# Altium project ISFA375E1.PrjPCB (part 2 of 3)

## Sheet ISFA375_DS_USB-C_CONN.SchDoc
size 431 x 279 mm; Date: Not shown in title block; ApprovedBy: Not shown in title block; CheckedBy: Not shown in title block; Author: Not shown in title block; CompanyName: Not shown in title block; DrawnBy: Thomas Mauer; Engineer: Not shown in title block; Organization: Not shown in title block; Address1: Not shown in title block; Address2: Not shown in title block; Address3: Not shown in title block; Address4: Not shown in title block; DocumentNumber: 4; Revision: Use project parameter SCH_Rev; SheetNumber: 4; SheetTotal: 11; PageSetup: Record=PageOptions¦CenterHorizontal=True¦CenterVertical=True¦PrintScale=1.00¦XCorrection=1.00¦YCorrection=1.00¦PrintKind=0¦BorderSize=5000000¦LeftOffset=0¦BottomOffset=0¦Orientation=2¦PaperLength=1000¦PaperWidth=1000¦Scale=100¦PaperSource=15¦PrintQuality=600¦MediaType=1¦DitherType=10¦PaperKind=Letter¦PrintScaleMode=1
Used 2 times, as channels DS1, DS2. Parts and nets are listed once, with the designators drawn on the sheet.
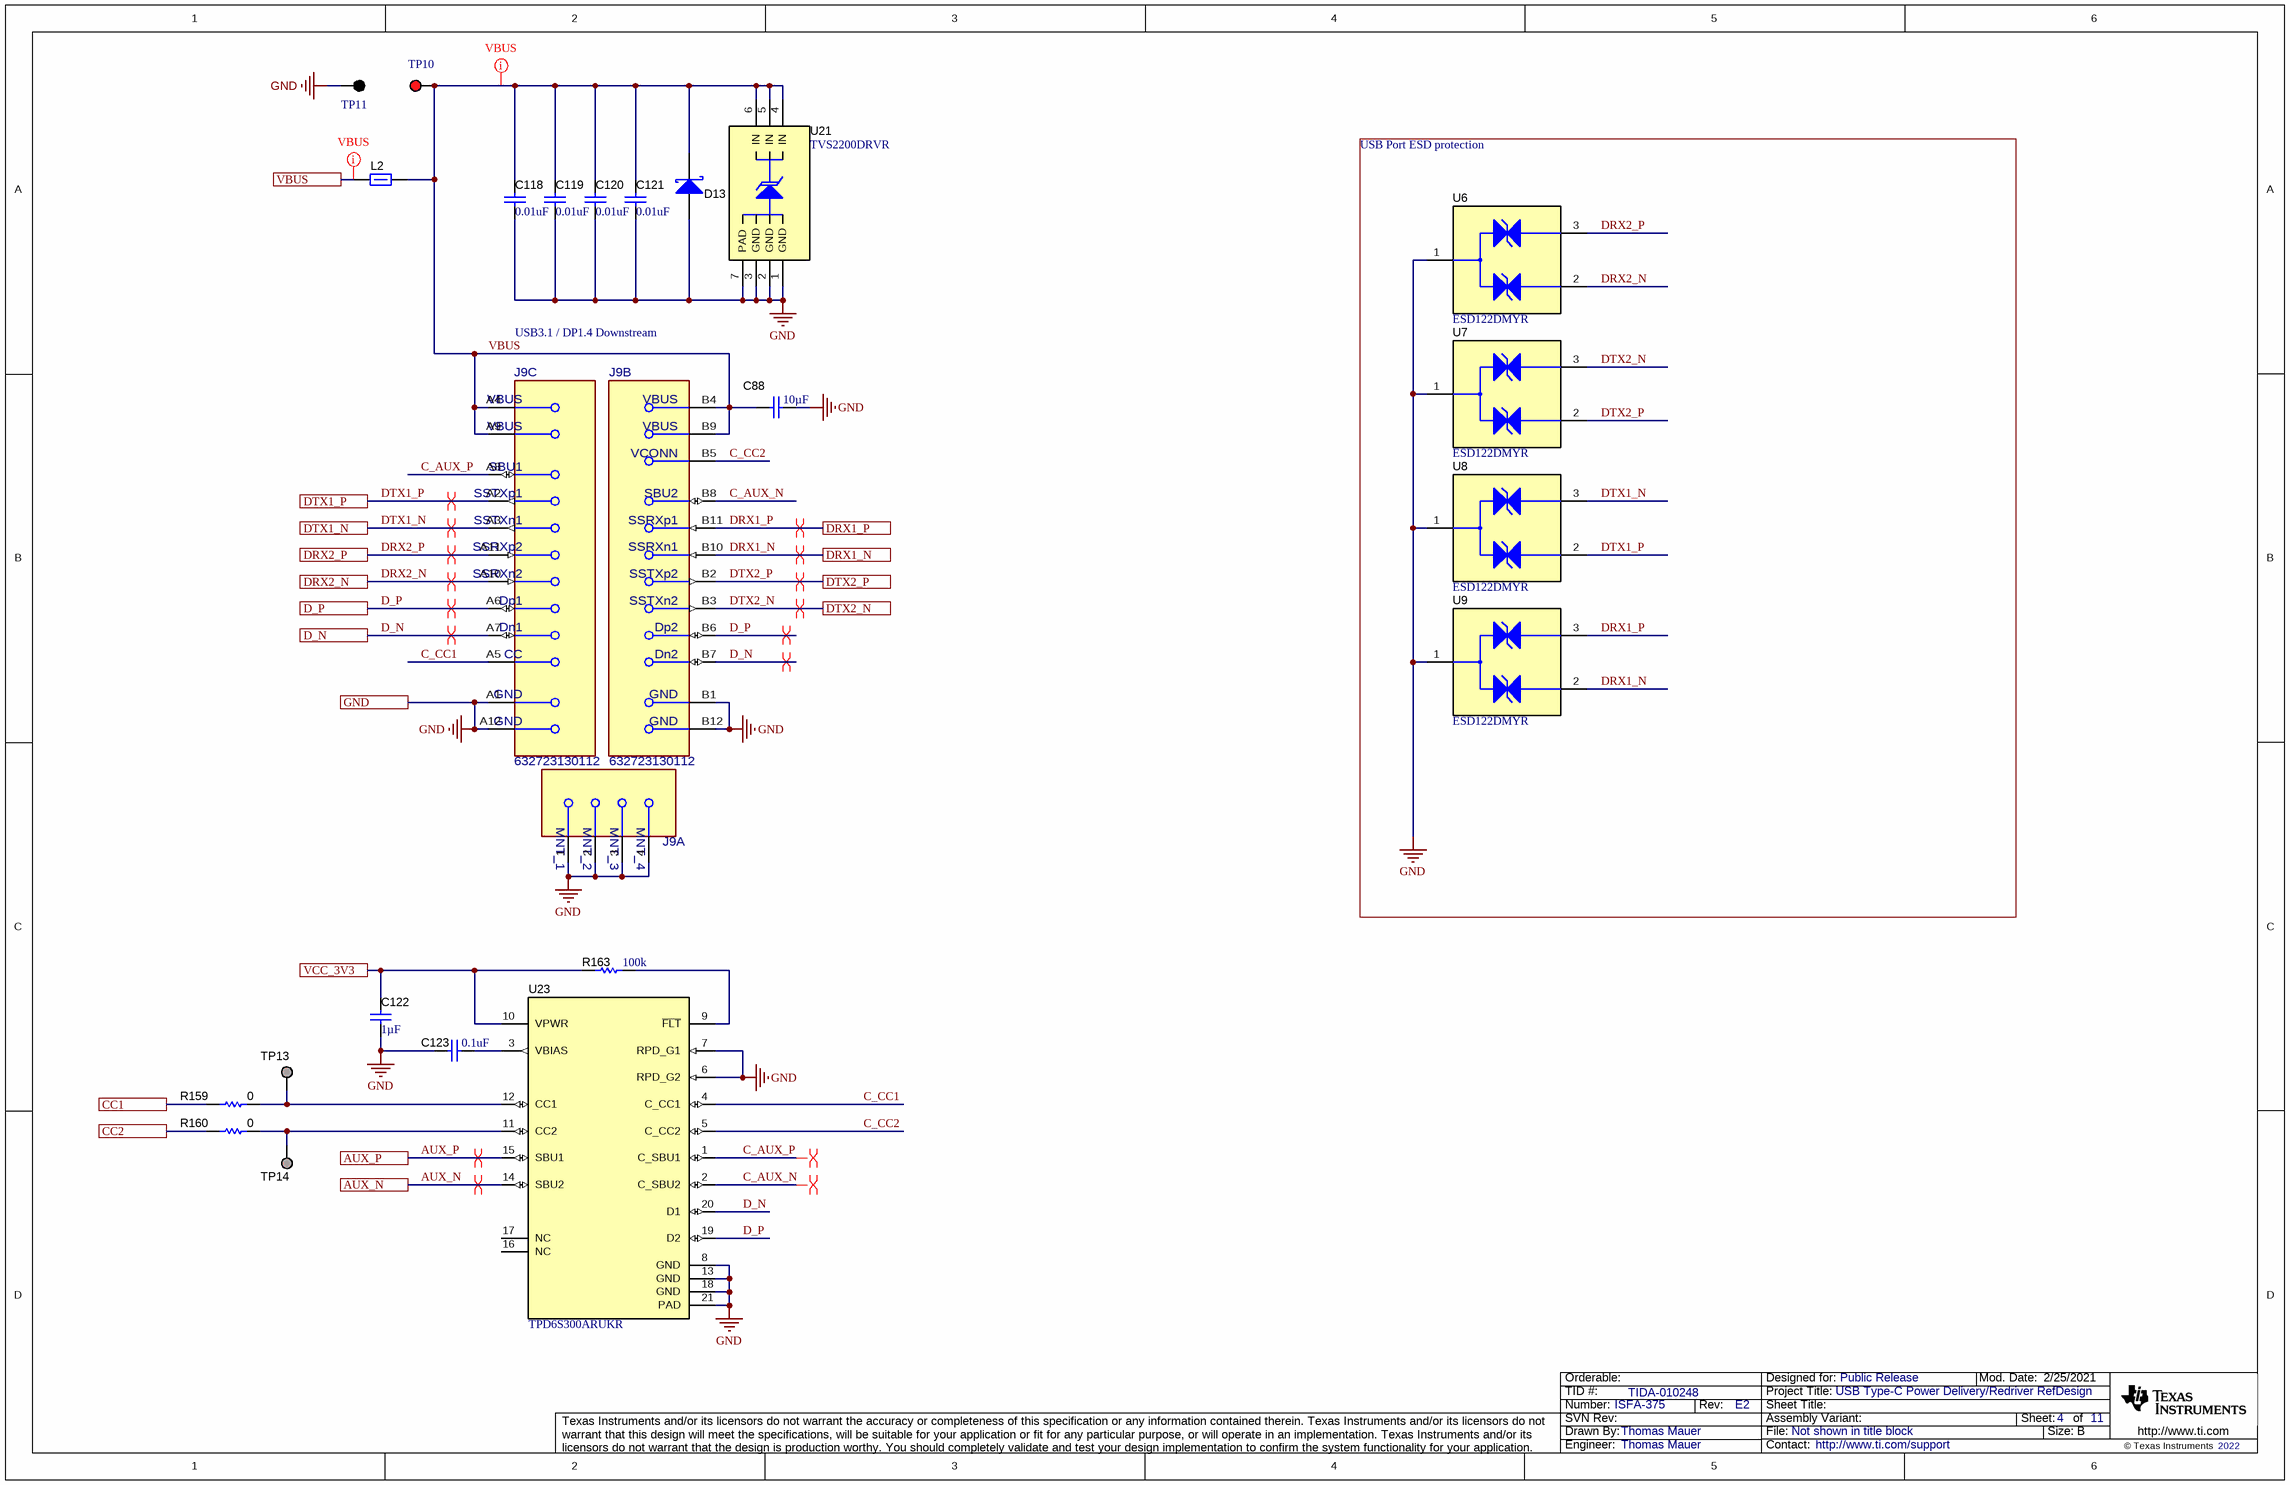
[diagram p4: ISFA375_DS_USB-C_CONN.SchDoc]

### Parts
C88  Cap_F: 10µF  [0805L]  (hidden comment: CL21B106KOQNNNE)
C118  ValueDisplayed: 0.01uF  [0402L]  (hidden comment: C0402C103J5RACTU)
C119  ValueDisplayed: 0.01uF  [0402L]  (hidden comment: C0402C103J5RACTU)
C120  ValueDisplayed: 0.01uF  [0402L]  (hidden comment: C0402C103J5RACTU)
C121  ValueDisplayed: 0.01uF  [0402L]  (hidden comment: C0402C103J5RACTU)
C122  ValueDisplayed: 1µF  [0603L]  (hidden comment: GRT188R61H105ME13D)
C123  ValueDisplayed: 0.1uF  [0402L]  (hidden comment: CGA2B3X7R1H104K050BB)
D13  NSR20F30NXT5G  [DSN2_0603]  (value not drawn)
J9  632723130112  [FP-632723130112_CONN_USB_9MM65_10MM0-MFG]  (value not drawn)  (parts A,B,C of 3)
L2  742792021  [0805L]  (value not drawn)
R159  ValueDisplayed: 0  [0201L]  (hidden comment: CRCW02010000Z0ED)
R160  ValueDisplayed: 0  [0201L]  (hidden comment: CRCW02010000Z0ED)
R163  ValueDisplayed: 100k  [0201L]  (hidden comment: CRCW0201100KFKED)
TP10  5005  [Keystone5005]  (value not drawn)
TP11  5006  [Keystone5006]  (value not drawn)
TP13  TESTPOINT  [TP_25MIL-SMT]  (value not drawn)  (no BOM)
TP14  TESTPOINT  [TP_25MIL-SMT]  (value not drawn)  (no BOM)
U6  ESD122DMYR  [DMY0003A]
U7  ESD122DMYR  [DMY0003A]
U8  ESD122DMYR  [DMY0003A]
U9  ESD122DMYR  [DMY0003A]
U21  TVS2200DRVR  [DRV0006A]
U23  TPD6S300ARUKR  [RUK0020B]

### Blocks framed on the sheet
USB Port ESD protection: U6-U9

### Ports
AUX_N, AUX_P, CC1, CC2, D_N, D_P, DRX1_N, DRX1_P, DRX2_N, DRX2_P, DTX1_N, DTX1_P, DTX2_N, DTX2_P, GND, VBUS, VCC_3V3

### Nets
GND: C88.1 C118.2 C119.2 C120.2 C121.2 C122.2 C123.1 D13.2(A) J9.1(MNT_1) J9.2(MNT_2) J9.3(MNT_3) J9.4(MNT_4) J9.A1(GND) J9.A12(GND) J9.B1(GND) J9.B12(GND) TP11.1 U6.1(GND) U7.1(GND) U8.1(GND) U9.1(GND) U21.1(GND) U21.2(GND) U21.3(GND) U21.7(PAD) U23.6(RPD_G2) U23.7(RPD_G1) U23.8(GND) U23.13(GND) U23.18(GND) U23.21(PAD) ; port GND
AUX_N: U23.14(SBU2) ; port AUX_N
AUX_P: U23.15(SBU1) ; port AUX_P
C_AUX_N: J9.B8(SBU2) U23.2(C_SBU2)
C_AUX_P: J9.A8(SBU1) U23.1(C_SBU1)
C_CC1: J9.A5(CC) U23.4(C_CC1)
C_CC2: J9.B5(VCONN) U23.5(C_CC2)
CC1: R159.1 ; port CC1
CC2: R160.1 ; port CC2
D_N: J9.A7(Dn1) J9.B7(Dn2) U23.20(D1) ; port D_N
D_P: J9.A6(Dp1) J9.B6(Dp2) U23.19(D2) ; port D_P
DRX1_N: J9.B10(SSRXn1) U9.2(IO2) ; port DRX1_N
DRX1_P: J9.B11(SSRXp1) U9.3(IO1) ; port DRX1_P
DRX2_N: J9.A10(SSRXn2) U6.2(IO2) ; port DRX2_N
DRX2_P: J9.A11(SSRXp2) U6.3(IO1) ; port DRX2_P
DTX1_N: J9.A3(SSTXn1) U8.3(IO1) ; port DTX1_N
DTX1_P: J9.A2(SSTXp1) U8.2(IO2) ; port DTX1_P
DTX2_N: J9.B3(SSTXn2) U7.3(IO1) ; port DTX2_N
DTX2_P: J9.B2(SSTXp2) U7.2(IO2) ; port DTX2_P
VBUS: C88.2 C118.1 C119.1 C120.1 C121.1 D13.1(K) J9.A4(VBUS) J9.A9(VBUS) J9.B4(VBUS) J9.B9(VBUS) L2.2 TP10.1 U21.4(IN) U21.5(IN) U21.6(IN)
VBUS: L2.1 ; port VBUS  [a separate net that carries the same name]
VCC_3V3: C122.1 R163.1 U23.10(VPWR) ; port VCC_3V3
NetC123_2: C123.2 U23.3(VBIAS)
NetR159_2: R159.2 TP13.1 U23.12(CC1)
NetR160_2: R160.2 TP14.1 U23.11(CC2)
NetR163_2: R163.2 U23.9(~{FLT})

Not connected (* = marked no-connect by the designer): U23 16(NC) 17(NC)

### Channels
DS1: designators end in _DS1; ports AUX_N=AUX_N AUX_P=AUX_P CC1=PA_CC1 CC2=PA_CC2 D_N=D1_D_N D_P=D1_D_P DRX1_N=D1_RX1_N DRX1_P=D1_RX1_P DRX2_N=D1_RX2_N DRX2_P=D1_RX2_P DTX1_N=D1_TX1_N DTX1_P=D1_TX1_P DTX2_N=D1_TX2_N DTX2_P=D1_TX2_P GND=GND VBUS=PA_VBUS VCC_3V3=VCC_3.3V
DS2: designators end in _DS2; ports AUX_N=AUX_N AUX_P=AUX_P CC1=PB_CC1 CC2=PB_CC2 D_N=D1_D_N D_P=D1_D_P DRX1_N=D2_RX1_N DRX1_P=D2_RX1_P DRX2_N=D2_RX2_N DRX2_P=D2_RX2_P DTX1_N=D2_TX1_N DTX1_P=D2_TX1_P DTX2_N=D2_TX2_N DTX2_P=D2_TX2_P GND=GND VBUS=PB_VBUS VCC_3V3=VCC_3.3V

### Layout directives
differential pair: AUX_N, AUX_P, C_AUX_N_DS1, C_AUX_P_DS1
differential pair; net class Diff_pairs: D1_D_N, D1_D_P, D1_RX1_N, D1_RX1_P, D1_RX2_N, D1_RX2_P, D1_TX1_N, D1_TX1_P, D1_TX2_N, D1_TX2_P
net class vbus: PA_VBUS, VBUS_DS1

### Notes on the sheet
- USB3.1 / DP1.4 Downstream

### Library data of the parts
C88 = CMP-0007995-2: CAP, CERM, 10 uF, 50V V, +/- 10%, X7R, 0805; Manufacturer: Samsung Electro-Mechanics; TaMin_C: -55°C; Polarized: N; SizeAreaWB_mm2: 6.75; Value1: Unknown; U/M: EA; Value: 10uF; TaMax_C: 125°C; SizeZ_mm: 1.45; SizeX_mm: 2; SizeY_mm: 1.25; Cap_Case: 0805; Value2: 16V; SizeArea_mm2: 2.5; AEC Category: Q200
C118-C121 = CMP-0006236-2: CAP, CERM, 0.01 uF, 50 V, +/- 5%, X7R, 0402; Manufacturer: Kemet; TaMin_C: -55°C; Polarized: N; SizeAreaWB_mm2: 3; Value1: Unknown; U/M: EA; Value: 0.01uF; TaMax_C: 125°C; SizeZ_mm: 0.6; SizeX_mm: 1; SizeY_mm: 0.5; Cap_Case: 0402; Value2: 50V; Cap_F: 10nF; AEC Category: Q200
C122 = CMP-0081784-1: CAP, CERM, 1 µF, 50 V,+/- 20%, X5R, AEC-Q200 Grade 3, 0603; Manufacturer: MuRata; TaMin_C: -55°C; Polarized: N; SizeAreaWB_mm2: 4.68; U/M: EA; Value: 1uF; TaMax_C: 85°C; SizeZ_mm: 1; SizeX_mm: 1.6; SizeY_mm: 0.8; Cap_Case: 0603; Value2: 50V; SizeArea_mm2: 1.28; AEC Qualified: Y; AEC Grade: 3; AEC Category: Q200
C123 = CMP-0006325-2: CAP, CERM, 0.1 uF, 50 V, +/- 10%, X7R, AEC-Q200 Grade 1, 0402; Manufacturer: TDK; TaMin_C: -55°C; ESR_ohm: 0.039064; Polarized: N; SizeAreaWB_mm2: 3; Value1: 0.039064 ohm; U/M: EA; Value: 0.1uF; TaMax_C: 125°C; SizeZ_mm: 0.6; SizeX_mm: 1; SizeY_mm: 0.5; Cap_Case: 0402; Value2: 50V; AEC Qualified: Y; Cap_F: 100nF; IRMS_A: 8.14669dA; AEC Category: Q200
D13 = CMP-0028829-2: Diode, Schottky, 30 V, 2 A, 2-XFDFN; Manufacturer: ON Semiconductor; Value2: 0.48V; SizeY_mm: 0.8; Value: 30V; TJmax_C: 150°C; Green_Lifecycle: Not Set; SizeAreaWB_mm2: 4.68; Value1: 2A; SizeArea_mm2: 1.28; Green_REACh: Incomplete; AEC Category: Q101; SizeZ_mm: 0.31; Vf_V: 480mV; AEC Qualified: N; SizeX_mm: 1.6
J9 = CMP-0093331-1: USB-C (USB TYPE-C) USB 3.2 Gen 2 (USB 3.1 Gen 2, Superspeed + (USB 3.1)) Receptacle Connector 24 Position Board Edge, Cutout; Surface Mount; Through Hole, Right Angle; Manufacturer: Wurth Electronics; SizeZ_mm: 3.52mm; AEC Qualified: No; Is Female: yes; Usb Standard: USB 3.1; Voltage_V: 20V; Shrouded: true; ContactFinish: Gold,Nickel; Current_A: 5A; Conn Orientation: Horizontal
L2 = CMP-0003072-1: Ferrite Bead, 22 ohm @ 100 MHz, 6 A, 0805; Manufacturer: Wurth Elektronik; Ztyp@1GHz_Ohm: 40.219; ZTyp@100MHz_Ohm: 22; SizeAreaWB_mm2: 6.75; DCR_ohm: 8m; Value1: 0.008 ohm; Value: 22 ohm; Imax_A: 6A; SizeZ_mm: 1.45; SizeX_mm: 2; SizeY_mm: 1.25; SizeArea_mm2: 2.5
R159 R160 = CMP-0027008-4: RES, 0, 5%, 0.05 W, 0201; Manufacturer: Vishay-Dale; Power_W: 50mW; TempCo: ppm/C; Value_Code: 0000; Value: 0; EIA_Code: E24; SizeX_mm: 0.6; SizeY_mm: 0.3; SizeZ_mm: 0.26; Value2: 0.05W; SizeArea_mm2: 0.18; AEC Qualified: N; AEC Category: Q200
R163 = CMP-0027261-3: RES, 100 k, 1%, 0.05 W, 0201; Manufacturer: Vishay-Dale; Power_W: 50mW; TempCo: 100 ppm/C; Value: 100k; EIA_Code: E96; SizeX_mm: 0.6; SizeY_mm: 0.3; SizeZ_mm: 0.26; Value2: 0.05W; SizeArea_mm2: 0.18; AEC Qualified: N; VDC_V: 30V; AEC Category: Q200
TP10 = CMP-0055142-1: Test Point, Compact, Red, TH; Manufacturer: Keystone; CNHeader: FALSE; Green_Lifecycle: Active; Green_REACh: Passed; ContactFinish: Silver; CT: TRUE
TP11 = CMP-0055143-2: Test Point, Compact, Black, TH; Manufacturer: Keystone Electronics; ContactFinish: Silver; Green_Lifecycle: Active; Green_REACh: Passed; CT: TRUE; CNHeader: FALSE
TP13 TP14 = CMP-0078143-3: TEST POINT.  No entry in BOM.
U6-U9 = CMP-0013358-2: 2-Channel ESD Protection Diode for USB Type-C and HDMI 2.0, DMY0003A (X1SON-3); Manufacturer: Texas Instruments; SizeX_mm: 0.6; SizeY_mm: 1.3; CompType: IC; SizeZ_mm: 0.4; SizeArea_mm2: 0.78; SizeAreaWB_mm2: 3.68; U/M: EA
U21 = CMP-0077834-1: 22-V Precision Surge Protection Clamp, DRV0006A (WSON-6); Alternate Manufacturer: Texas Instruments; SizeAreaWB_mm2: 9.0; SizeZ_mm: 0.8; SizeX_mm: 2.0; SizeArea_mm2: 4.0; CompType: IC; AEC Qualified: N; AEC Category: Q200
U23 = CMP-0081565-1: USB Type-C Port Protector: Short-to-VBUS Overvoltage and IEC ESD Protection, RUK0020B (WQFN-20); Alternate Manufacturer: Texas Instruments; SizeAreaWB_mm2: 16; SizeZ_mm: 0.8; SizeX_mm: 3; SizeArea_mm2: 9; CompType: IC; AEC Qualified: N; AEC Category: Q200

## Sheet ISFA375_SYSTEM_POWER.SchDoc
size 431 x 279 mm; Date: Not shown in title block; ApprovedBy: Not shown in title block; CheckedBy: Not shown in title block; Author: Not shown in title block; CompanyName: Not shown in title block; DrawnBy: Thomas Mauer; Engineer: Not shown in title block; Organization: Not shown in title block; Address1: Not shown in title block; Address2: Not shown in title block; Address3: Not shown in title block; Address4: Not shown in title block; DocumentNumber: 9; Revision: Use project parameter SCH_Rev; SheetNumber: 9; SheetTotal: 11; PageSetup: Record=PageOptions¦CenterHorizontal=True¦CenterVertical=True¦PrintScale=1.00¦XCorrection=1.00¦YCorrection=1.00¦PrintKind=0¦BorderSize=5000000¦LeftOffset=0¦BottomOffset=0¦Orientation=2¦PaperLength=1000¦PaperWidth=1000¦Scale=100¦PaperSource=15¦PrintQuality=600¦MediaType=1¦DitherType=10¦PaperKind=Letter¦PrintScaleMode=1
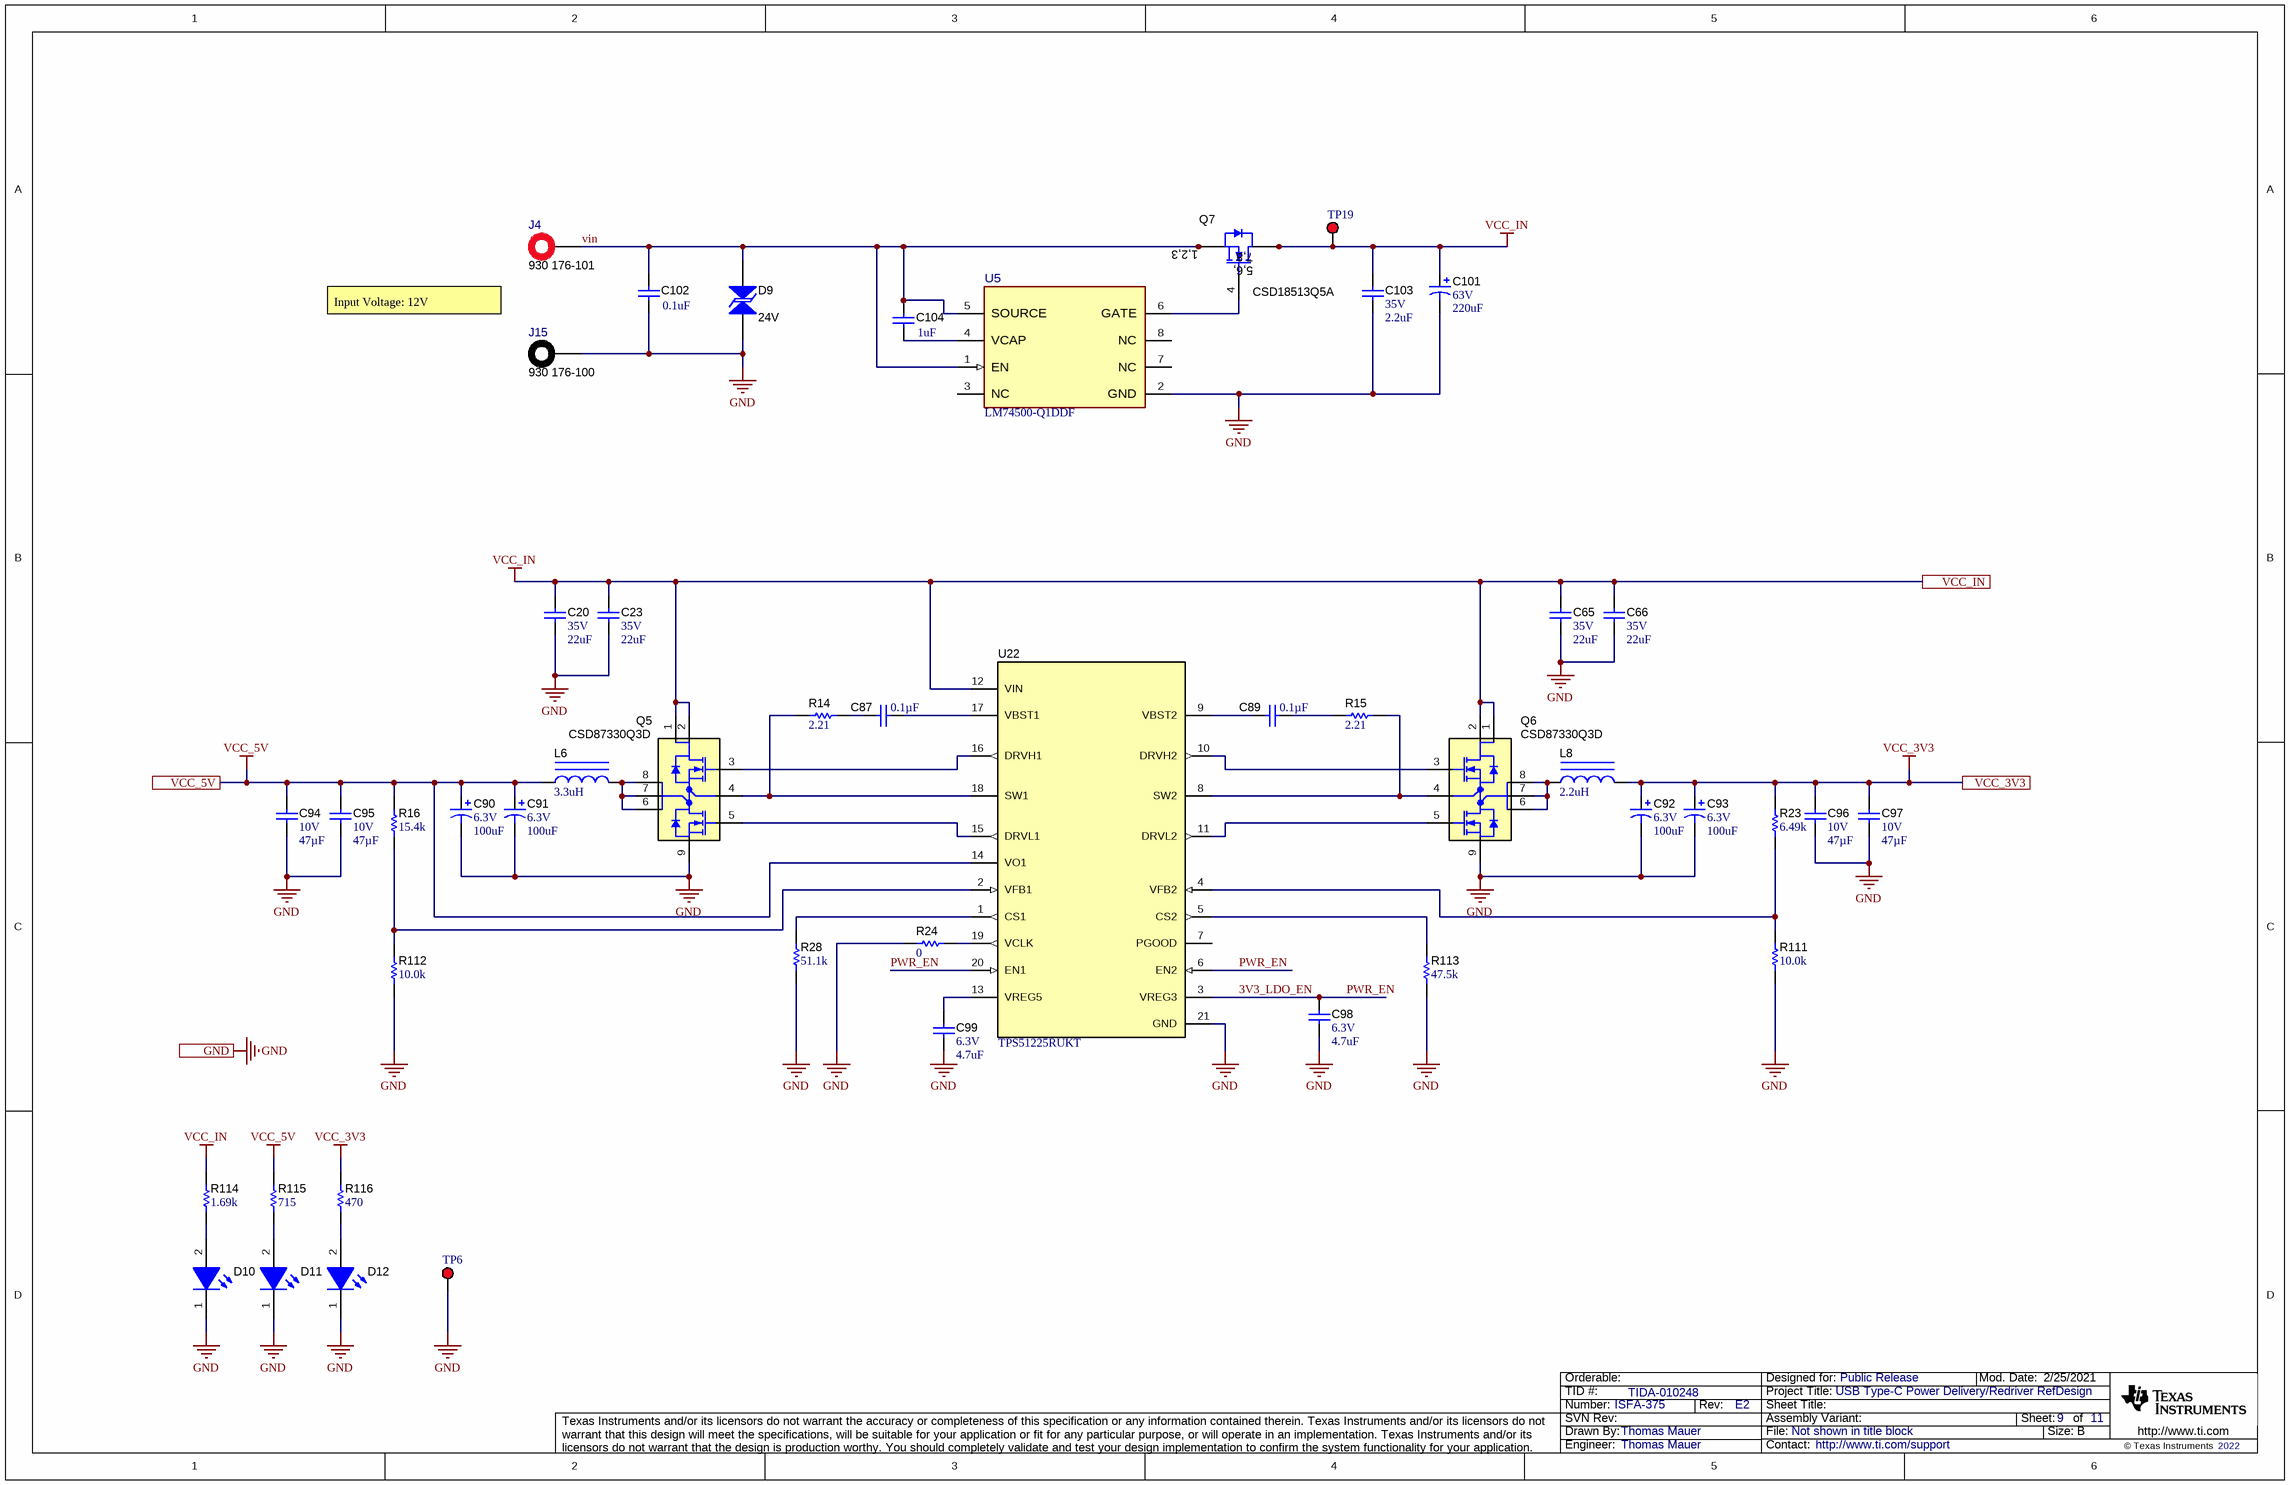
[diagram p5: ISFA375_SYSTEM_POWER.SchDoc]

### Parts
C20  VDC_V: 35V  ValueDisplayed: 22uF  [0805L]  (hidden comment: C2012X5R1V226M125AC)
C23  VDC_V: 35V  ValueDisplayed: 22uF  [0805L]  (hidden comment: C2012X5R1V226M125AC)
C65  VDC_V: 35V  ValueDisplayed: 22uF  [0805L]  (hidden comment: C2012X5R1V226M125AC)
C66  VDC_V: 35V  ValueDisplayed: 22uF  [0805L]  (hidden comment: C2012X5R1V226M125AC)
C87  ValueDisplayed: 0.1µF  [0201_033L]  (hidden comment: GRM033R61A104KE84D)
C89  ValueDisplayed: 0.1µF  [0201_033L]  (hidden comment: GRM033R61A104KE84D)
C90  VDC_V: 6.3V  ValueDisplayed: 100uF  [3528-21]  (hidden comment: T520B107M006ATE015)
C91  VDC_V: 6.3V  ValueDisplayed: 100uF  [3528-21]  (hidden comment: T520B107M006ATE015)
C92  VDC_V: 6.3V  ValueDisplayed: 100uF  [3528-21]  (hidden comment: T520B107M006ATE015)
C93  VDC_V: 6.3V  ValueDisplayed: 100uF  [3528-21]  (hidden comment: T520B107M006ATE015)
C94  VDC_V: 10V  ValueDisplayed: 47µF  [0805L]  (hidden comment: GRM21BR61A476ME15L)
C95  VDC_V: 10V  ValueDisplayed: 47µF  [0805L]  (hidden comment: GRM21BR61A476ME15L)
C96  VDC_V: 10V  ValueDisplayed: 47µF  [0805L]  (hidden comment: GRM21BR61A476ME15L)
C97  VDC_V: 10V  ValueDisplayed: 47µF  [0805L]  (hidden comment: GRM21BR61A476ME15L)
C98  VDC_V: 6.3V  ValueDisplayed: 4.7uF  [0402L]  (hidden comment: GRM155R60J475ME47D)
C99  VDC_V: 6.3V  ValueDisplayed: 4.7uF  [0402L]  (hidden comment: GRM155R60J475ME47D)
C101  VDC_V: 63V  ValueDisplayed: 220uF  [SM_RADIAL_H13]  (hidden comment: EEV-FK1J221Q)
C102  ValueDisplayed: 0.1uF  [0402L]  (hidden comment: GCM155R71H104KE02D)
C103  VDC_V: 35V  ValueDisplayed: 2.2uF  [0603L]  (hidden comment: GRM188R6YA225KA12D)
C104  ValueDisplayed: 1uF  [0402L]  (hidden comment: GRM155R6YA105KE11D)
D9  value 24V  [SOD-323-Bi]  (hidden comment: PESD24VL1BA,115)
D10  150060VS75000  [WL-SMCW_GREEN]  (value not drawn)
D11  150060VS75000  [WL-SMCW_GREEN]  (value not drawn)
D12  150060VS75000  [WL-SMCW_GREEN]  (value not drawn)
J4  930 176-101  [Hirschmann_930_176-101]
J15  930 176-100  [Hirschmann_930_176-100]
L6  ValueDisplayed: 3.3uH  [WE-HCI_7050]  (hidden comment: 744314330)
L8  ValueDisplayed: 2.2uH  [WE-LHMI_4020]  (hidden comment: 74437324022)
Q5  CSD87330Q3D  [DQZ0008A]
Q6  CSD87330Q3D  [DQZ0008A]
Q7  CSD18513Q5A  [DQJ0008A]
R14  ValueDisplayed: 2.21  [0201L]  (hidden comment: CRCW02012K20FKED)
R15  ValueDisplayed: 2.21  [0201L]  (hidden comment: CRCW02012K20FKED)
R16  ValueDisplayed: 15.4k  [0201L]  (hidden comment: CRCW020115K4FKED)
R23  ValueDisplayed: 6.49k  [0201L]  (hidden comment: RC0201FR-076K49L)
R24  ValueDisplayed: 0  [0201L]  (hidden comment: CRCW02010000Z0ED)
R28  ValueDisplayed: 51.1k  [0201L]  (hidden comment: RC0201FR-0751K1L)
R111  ValueDisplayed: 10.0k  [0201L]  (hidden comment: CRCW020110K0FKED)
R112  ValueDisplayed: 10.0k  [0201L]  (hidden comment: CRCW020110K0FKED)
R113  ValueDisplayed: 47.5k  [0201L]  (hidden comment: RC0201FR-7D47K5L)
R114  ValueDisplayed: 1.69k  [0201L]  (hidden comment: RC0201FR-071K69L)
R115  ValueDisplayed: 715  [0201L]  (hidden comment: RC0201FR-07715RL)
R116  ValueDisplayed: 470  [0201L]  (hidden comment: RC0201FR-07470RL)
TP6  5005  [Keystone5005]  (value not drawn)
TP19  5005  [Keystone5005]  (value not drawn)
U5  LM74500-Q1DDF  [DDF0008A-MFG]
U22  TPS51225RUKT  [RUK0020B]

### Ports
GND, VCC_3V3, VCC_5V, VCC_IN

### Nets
GND: C20.2 C23.2 C65.2 C66.2 C90.2(-) C91.2(-) C92.2(-) C93.2(-) C94.2 C95.2 C96.2 C97.2 C98.2 C99.2 C101.2(-) C102.2 C103.2 D9.1 D10.1(K) D11.1(K) D12.1(K) J15.1 Q5.9(PGND) Q6.9(PGND) R24.1 R28.1 R111.1 R112.1 R113.1 TP6.1 U5.2(GND) U22.21(GND) ; port GND
VCC_3V3: C92.1(+) C93.1(+) C96.1 C97.1 L8.2 R23.2 R116.2 ; port VCC_3V3  [project net VCC_3.3V]
VCC_5V: C90.1(+) C91.1(+) C94.1 C95.1 L6.1 R16.2 R115.2 U22.14(VO1) ; port VCC_5V
VCC_IN: C20.1 C23.1 C65.1 C66.1 C101.1(+) C103.1 Q5.1(VIN) Q5.2(VIN) Q6.1(VIN) Q6.2(VIN) Q7.5(D) Q7.6(D) Q7.7(D) Q7.8(D) Q7.9(D) R114.2 TP19.1 U22.12(VIN) ; port VCC_IN
3V3_LDO_EN: C98.1 U22.3(VREG3) U22.6(EN2) U22.20(EN1)  [also labelled PWR_EN]
vin: C102.1 C104.1 D9.2 J4.1 Q7.1(S) Q7.2(S) Q7.3(S) U5.1(EN) U5.5(SOURCE)
NetC87_1: C87.1 U22.17(VBST1)
NetC87_2: C87.2 R14.2
NetC89_1: C89.1 R15.1
NetC89_2: C89.2 U22.9(VBST2)
NetC99_1: C99.1 U22.13(VREG5)
NetC104_2: C104.2 U5.4(VCAP)
NetD10_2: D10.2(A) R114.1
NetD11_2: D11.2(A) R115.1
NetD12_2: D12.2(A) R116.1
NetL6_2: L6.2 Q5.6(VSW) Q5.7(VSW) Q5.8(VSW)
NetL8_1: L8.1 Q6.6(VSW) Q6.7(VSW) Q6.8(VSW)
NetQ5_3: Q5.3(TG) U22.16(DRVH1)
NetQ5_4: Q5.4(TGR) R14.1 U22.18(SW1)
NetQ5_5: Q5.5(BG) U22.15(DRVL1)
NetQ6_3: Q6.3(TG) U22.10(DRVH2)
NetQ6_4: Q6.4(TGR) R15.2 U22.8(SW2)
NetQ6_5: Q6.5(BG) U22.11(DRVL2)
NetQ7_4: Q7.4(G) U5.6(GATE)
NetR16_1: R16.1 R112.2 U22.2(VFB1)
NetR23_1: R23.1 R111.2 U22.4(VFB2)
NetR24_2: R24.2 U22.19(VCLK)
NetR28_2: R28.2 U22.1(CS1)
NetR113_2: R113.2 U22.5(CS2)

Not connected (* = marked no-connect by the designer): U5 3(NC) 7(NC) 8(NC); U22 7(PGOOD)

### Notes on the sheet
- Input Voltage: 12V

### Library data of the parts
C20 C23 C65 C66 = CMP-0007844-2: CAP, CERM, 22 uF, 35 V, +/- 20%, X5R, 0805; Manufacturer: TDK; TaMin_C: -55°C; ESR_ohm: 2.05m; Polarized: N; SizeAreaWB_mm2: 6.75; Value1: 0.00205 ohm; U/M: EA; Value: 22uF; TaMax_C: 85°C; SizeZ_mm: 1.45; SizeX_mm: 2; SizeY_mm: 1.25; Cap_Case: 0805; SizeArea_mm2: 2.5; Cap_F: 22µF; IRMS_A: 4.55587A; AEC Category: Q200
C87 C89 = CMP-0086059-1: CAP, CERM, 0.1 µF, 10 V,+/- 10%, X5R, 0201; Manufacturer: MuRata; AEC Category: Q200; Cap_F: 100nF; Value: 0.1uF; SizeY_mm: 0.3; AEC Qualified: N; SizeAreaWB_mm2: 2.08; Cap_Case: 0201; VDC_V: 10V; SizeArea_mm2: 0.18; SizeZ_mm: 0.33; SizeX_mm: 0.6; TaMax_C: 85°C; TaMin_C: -55°C; U/M: EA
C90-C93 = CMP-0011556-2: CAP, TA, 100 uF, 6.3 V, +/- 20%, 0.015 ohm, SMD; Manufacturer: Kemet; TaMin_C: -55°C; ESR_ohm: 0.015; Polarized: Y; SizeAreaWB_mm2: 17.1; U/M: EA; Value: 100uF; TaMax_C: 105°C; SizeZ_mm: 2.1; SizeX_mm: 3.5; SizeY_mm: 2.8; SizeArea_mm2: 9.8; CompType: Capacitor; AEC Qualified: N; Cap_F: 100µF; IRMS_A: 2.9A; AEC Category: Q200
C94-C97 = CMP-0078699-1: CAP, CERM, 47 µF, 10 V,+/- 20%, X5R, 0805; Manufacturer: MuRata; TaMin_C: -55°C; Polarized: N; Green_Lifecycle: Active; SizeAreaWB_mm2: 6.75; Green_REACh: Passed; U/M: EA; Value: 47uF; TaMax_C: 85°C; SizeZ_mm: 1.45; SizeX_mm: 2; SizeY_mm: 1.25; Cap_Case: 0805; SizeArea_mm2: 2.5; AEC Category: Q200
C98 C99 = CMP-0006552-2: CAP, CERM, 4.7 uF, 6.3 V, +/- 20%, X5R, 0402; Manufacturer: MuRata; TaMin_C: -55°C; Polarized: N; SizeAreaWB_mm2: 3; Value1: Unknown; U/M: EA; Value: 4.7uF; TaMax_C: 85°C; SizeZ_mm: 0.6; SizeX_mm: 1; SizeY_mm: 0.5; Cap_Case: 0402; Cap_F: 4.7µF; AEC Category: Q200
C101 = CMP-0011214-2: CAP, AL, 220 uF, 63 V, +/- 20%, 0.16 ohm, AEC-Q200 Grade 2, SMD; Manufacturer: Panasonic; TaMin_C: -55°C; ESR_ohm: 1.6d; Polarized: Y; SizeAreaWB_mm2: 263.5; U/M: EA; Value: 220uF; TaMax_C: 105°C; SizeZ_mm: 13.5; SizeX_mm: 15; Cap_Case: H13; SizeArea_mm2: 202.5; CompType: Capacitor; Cap_F: 220µF; IRMS_A: 8dA; AEC Grade: 2; AEC Category: Q200
C102 = CMP-0006356-2: CAP, CERM, 0.1 uF, 50 V, +/- 10%, X7R, AEC-Q200 Grade 1, 0402; Manufacturer: MuRata; TaMin_C: -55°C; Polarized: N; SizeAreaWB_mm2: 3; Value1: Unknown; U/M: EA; Value: 0.1uF; TaMax_C: 125°C; SizeZ_mm: 0.6; SizeX_mm: 1; SizeY_mm: 0.5; Cap_Case: 0402; Value2: 50V; AEC Qualified: Y; Cap_F: 100nF; AEC Category: Q200
C103 = CMP-0007356-5: CAP, CERM, 2.2 uF, 35 V, +/- 10%, X5R, 0603; Manufacturer: MuRata; TaMin_C: -55°C; Polarized: N; SizeAreaWB_mm2: 4.68; Value1: Unknown; U/M: EA; Value: 2.2uF; TaMax_C: 85°C; SizeZ_mm: 1; SizeX_mm: 1.6; SizeY_mm: 0.8; Cap_Case: 0603; SizeArea_mm2: 1.28; Cap_F: 2.2µF; AEC Category: Q200
C104 = CMP-0006619-2: CAP, CERM, 1 uF, 35 V, +/- 10%, X5R, 0402; Manufacturer: MuRata; TaMin_C: -55°C; Polarized: N; SizeAreaWB_mm2: 3; Value1: Unknown; U/M: EA; Value: 1uF; TaMax_C: 85°C; SizeZ_mm: 0.6; SizeX_mm: 1; SizeY_mm: 0.5; Cap_Case: 0402; Value2: 35V; Cap_F: 1µF; AEC Category: Q200
D9 = CMP-0006061-5: Diode, TVS, Bi, 24 V, 70 Vc, SOD323; Manufacturer: NXP Semiconductor; Vc: 70V; Vbr_Min: 25.4V; AEC Category: Q101; Ppk: 200W; Ipp: 3A; AEC Qualified: N; Vbr_Max: 30.3V
D10-D12 = CMP-0002894-2: LED, Green, SMD; Manufacturer: Wurth Elektronik; Type: AlInGaP; Value2: 2V; Io_A: 20mA; Value1: W
J4 = CMP-0084861-2: Banana Jack BIL 20 Red, TH; Manufacturer: Hirschmann; Voltage_V: 60V; Row_Count: 1; Gender: Female; Current_A: 32A
J15 = CMP-0084860-2: Banana Jack BIL 20 Black, TH; Manufacturer: Hirschmann; Voltage_V: 60V; Current_A: 32A; Gender: Female; Row_Count: 1
L6 = CMP-0063942-1: Inductor, Shielded Drum Core, Superflux, 3.3 uH, 8 A, 0.0096 ohm, SMD; Manufacturer: Wurth Elektronik; Isat: 8A @ 30% inductance drop; Irms: 9A @ 50C rise; Green_Lifecycle: Active; SizeAreaWB_mm2: 80.1; DCR_ohm: 9.6m; Green_REACh: Passed; Value: 3.3uH; Imax_A: 8A; SizeZ_mm: 5; SizeX_mm: 7; SizeY_mm: 6.9; SizeArea_mm2: 48.3; Ind_H: 3.3µH; AEC Category: Q200
L8 = CMP-0064074-1: Inductor, Shielded Drum Core, Powdered Iron, 2.2 uH, 3.25 A, 0.051 ohm, SMD; Manufacturer: Wurth Elektronik; Isat: 6.5A @ 20% inductance drop; Irms: 3.25A @ 40C rise; Green_Lifecycle: Active; SizeAreaWB_mm2: 27.577; DCR_ohm: 0.051; Green_REACh: Passed; Value: 2.2uH; Imax_A: 3.25A; SizeZ_mm: 2; SizeX_mm: 4.45; SizeY_mm: 4.06; SizeArea_mm2: 18.067; Ind_H: 2.2µH; AEC Category: Q200
Q5 Q6 = CMP-0000596-1: MOSFET, 2-CH, N-CH, 30 V, 20 A, DQZ0008A (LSON-CLIP-8); Alternate Manufacturer: None; Manufacturer: Texas Instruments; SizeZ_mm: 1.6; ChType: N; Value2: 4.8 nC; Value1: 0.011; VdsMax_V: 30V; SizeX_mm: 3.3; Vgs_V: 10V; Value: 30V; Rdson45_ohm: 0.0113; SizeArea_mm2: 10.89; AEC Category: Q101; IdsMax_A: 20A; SizeAreaWB_mm2: 18.49; U/M: EA; QgTyp_nC: 4.8
Q7 = CMP-0000714-1: MOSFET, N-CH, 40 V, 100 A, DQJ0008A (VSONP-8); Alternate Manufacturer: None; Manufacturer: Texas Instruments; SizeZ_mm: 1.1; ChType: N; Value2: 47 nC; Value1: 0.004; VdsMax_V: 40V; SizeX_mm: 6; SizeAreaWB_mm2: 55.2; SizeY_mm: 4.9; Vgs_V: 20V; QgTyp_nC: 47; Value: 40V; Rdson45_ohm: 4.1m; SizeArea_mm2: 29.4; AEC Category: Q101; IdsMax_A: 100A; U/M: EA
R14 R15 = CMP-0027575-1: RES, 2.21, 1%, 0.05 W, 0201; Manufacturer: Yageo America; PartNumber: RC0201FR-072R21L; Power_W: 50mW; TempCo: 350 ppm/C; Value_Code: 2R21; U/M: EA; Value: 2.21; EIA_Code: E96; SizeX_mm: 0.6; SizeY_mm: 0.3; SizeZ_mm: 0.26; Value2: 0.05W; SizeArea_mm2: 0.18; AEC Qualified: N; VDC_V: 25V; AEC Category: Q200
R16 = CMP-0080844-1: RES, 15.4 k, 1%, 0.05 W, 0201; Manufacturer: Vishay-Dale; Power_W: 50mW; TempCo: 100 ppm/C; SizeAreaWB_mm2: 2.08; Value_Code: 15k4; Value: 15.4k; EIA_Code: E96; SizeX_mm: 0.6; SizeY_mm: 0.3; SizeZ_mm: 0.26; Value2: 0.05W; SizeArea_mm2: 0.18; AEC Qualified: N; VDC_V: 30V; AEC Category: Q200
R23 = CMP-0027845-1: RES, 6.49 k, 1%, 0.05 W, 0201; Manufacturer: Yageo America; Power_W: 50mW; TempCo: 200 ppm/C; Value_Code: 6k49; U/M: EA; Value: 6.49k; EIA_Code: E96; SizeX_mm: 0.6; SizeY_mm: 0.3; SizeZ_mm: 0.26; Value2: 0.05W; SizeArea_mm2: 0.18; AEC Qualified: N; VDC_V: 25V; AEC Category: Q200
R24 = CMP-0027008-4: as R159 on sheet ISFA375_DS_USB-C_CONN
R28 = CMP-0027756-1: RES, 51.1 k, 1%, 0.05 W, 0201; Manufacturer: Yageo America; Power_W: 50mW; TempCo: 200 ppm/C; Value_Code: 51k1; U/M: EA; Value: 51.1k; EIA_Code: E96; SizeX_mm: 0.6; SizeY_mm: 0.3; SizeZ_mm: 0.26; Value2: 0.05W; SizeArea_mm2: 0.18; AEC Qualified: N; VDC_V: 25V; AEC Category: Q200
R111 R112 = CMP-0027262-3: RES, 10.0 k, 1%, 0.05 W, 0201; Manufacturer: Vishay-Dale; Power_W: 50mW; TempCo: 100 ppm/C; Value_Code: 10k0; Value: 10.0k; EIA_Code: E96; Res_ohm: 10k; SizeX_mm: 0.6; SizeY_mm: 0.3; SizeZ_mm: 0.26; Value2: 0.05W; SizeArea_mm2: 0.18; AEC Qualified: N; VDC_V: 30V; AEC Category: Q200
R113 = CMP-0028023-1: RES, 47.5 k, 1%, 0.05 W, 0201; Manufacturer: Yageo America; Power_W: 50mW; TempCo: 200 ppm/C; Value_Code: 47k5; U/M: EA; Value: 47.5k; EIA_Code: E96; SizeX_mm: 0.6; SizeY_mm: 0.3; SizeZ_mm: 0.26; Value2: 0.05W; SizeArea_mm2: 0.18; AEC Qualified: N; VDC_V: 25V; AEC Category: Q200
R114 = CMP-0027444-1: RES, 1.69 k, 1%, 0.05 W, 0201; Manufacturer: Yageo America; Power_W: 50mW; TempCo: 200 ppm/C; Value_Code: 1k69; U/M: EA; Value: 1.69k; EIA_Code: E96; SizeX_mm: 0.6; SizeY_mm: 0.3; SizeZ_mm: 0.26; Value2: 0.05W; SizeArea_mm2: 0.18; AEC Qualified: N; VDC_V: 25V; AEC Category: Q200
R115 = CMP-0027857-1: RES, 715, 1%, 0.05 W, 0201; Manufacturer: Yageo America; Power_W: 50mW; TempCo: 200 ppm/C; Value_Code: 715R; U/M: EA; Value: 715; EIA_Code: E96; SizeX_mm: 0.6; SizeY_mm: 0.3; SizeZ_mm: 0.26; Value2: 0.05W; SizeArea_mm2: 0.18; AEC Qualified: N; VDC_V: 25V; AEC Category: Q200
R116 = CMP-0027719-1: RES, 470, 1%, 0.05 W, 0201; Manufacturer: Yageo America; Power_W: 50mW; TempCo: 200 ppm/C; Value_Code: 470R; U/M: EA; Value: 470; SizeX_mm: 0.6; SizeY_mm: 0.3; SizeZ_mm: 0.26; Value2: 0.05W; SizeArea_mm2: 0.18; AEC Qualified: N; VDC_V: 25V; AEC Category: Q200
TP6 TP19 = CMP-0055142-1: as TP10 on sheet ISFA375_DS_USB-C_CONN
U5 = CMP-0091365-1: Low IQ Reverse Battery Protection Controller, SOT23-8; Manufacturer: Texas Instruments; TJmax_C: +150°C; TaMax_C: +125°C; Nominal Supply Current: 80uA; Standoff Height: 0mm; AEC Grade: Grade 1; AEC Qualified: Yes; SizeZ_mm: 1.1mm; Max Supply Voltage: 60V; Min Supply Voltage: 4V; TaMin_C: -40°C; Number Of Outputs: 1
U22 = CMP-0081825-1: Dual Synchronous Step-Down Controller with 5-V and 3.3-V LDOs, RUK0020B (WQFN-20); Alternate PartNumber: TPS51225RUKR; Alternate Manufacturer: Texas Instruments; SizeAreaWB_mm2: 16; Rating: Catalog; SizeZ_mm: 0.8; SizeX_mm: 3; SizeArea_mm2: 9; CompType: IC; AEC Qualified: N; AEC Category: Q200

## Sheet ISFA375_BUS_POWER_TPS55288.SchDoc
size 431 x 279 mm; Date: Not shown in title block; ApprovedBy: Not shown in title block; CheckedBy: Not shown in title block; Author: Not shown in title block; CompanyName: Not shown in title block; DrawnBy: Thomas Mauer; Engineer: Not shown in title block; Organization: Not shown in title block; Address1: Not shown in title block; Address2: Not shown in title block; Address3: Not shown in title block; Address4: Not shown in title block; DocumentNumber: 8; Revision: Use project parameter SCH_Rev; SheetNumber: 8; SheetTotal: 11; PageSetup: Record=PageOptions¦CenterHorizontal=True¦CenterVertical=True¦PrintScale=1.00¦XCorrection=1.00¦YCorrection=1.00¦PrintKind=0¦BorderSize=5000000¦LeftOffset=0¦BottomOffset=0¦Orientation=2¦PaperLength=1000¦PaperWidth=1000¦Scale=100¦PaperSource=15¦PrintQuality=600¦MediaType=1¦DitherType=10¦PaperKind=Letter¦PrintScaleMode=1
Used 2 times, as channels V1, V2. Parts and nets are listed once, with the designators drawn on the sheet.
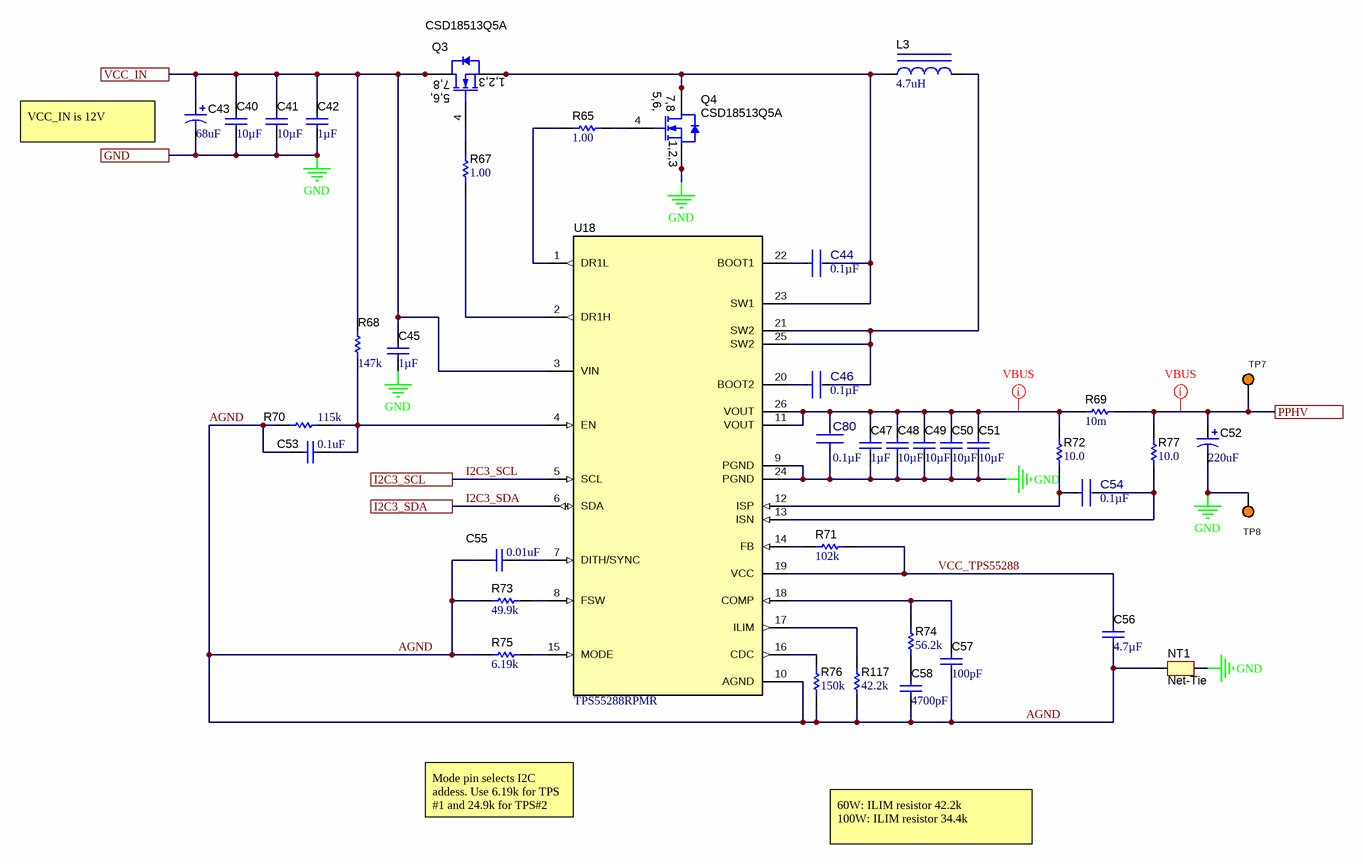
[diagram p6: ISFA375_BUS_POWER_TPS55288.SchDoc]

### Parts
C40  ValueDisplayed: 10µF  [1210_280]  (hidden comment: CGA6P1X7R1N106M250AC)
C41  ValueDisplayed: 10µF  [1210_280]  (hidden comment: CGA6P1X7R1N106M250AC)
C42  ValueDisplayed: 1µF  [0603L]  (hidden comment: GRT188R61H105ME13D)
C43  ValueDisplayed: 68uF  [SM_RADIAL_8MM]  (hidden comment: EEHZA1H680P)
C44  Cap_F: 0.1µF  [FP-GCM188L81H104KA57D_0603-MFG]  (hidden comment: GCM188L81H104KA57D)
C45  ValueDisplayed: 1µF  [0603L]  (hidden comment: GRT188R61H105ME13D)
C46  Cap_F: 0.1µF  [FP-GCM188L81H104KA57D_0603-MFG]  (hidden comment: GCM188L81H104KA57D)
C47  ValueDisplayed: 1µF  [0603L]  (hidden comment: GRT188R61H105ME13D)
C48  ValueDisplayed: 10µF  [1210_280]  (hidden comment: CGA6P1X7R1N106M250AC)
C49  ValueDisplayed: 10µF  [1210_280]  (hidden comment: CGA6P1X7R1N106M250AC)
C50  ValueDisplayed: 10µF  [1210_280]  (hidden comment: CGA6P1X7R1N106M250AC)
C51  ValueDisplayed: 10µF  [1210_280]  (hidden comment: CGA6P1X7R1N106M250AC)
C52  ValueDisplayed: 220uF  [SM_RADIAL_8MM]  (hidden comment: EEHZA1E221P)
C53  ValueDisplayed: 0.1uF  [0402L]  (hidden comment: CGA2B3X7R1H104K050BB)
C54  Cap_F: 0.1µF  [FP-GCM188L81H104KA57D_0603-MFG]  (hidden comment: GCM188L81H104KA57D)
C55  ValueDisplayed: 0.01uF  [0402L]  (hidden comment: CGA2B3X7R1H103K050BB)
C56  ValueDisplayed: 4.7µF  [0603L]  (hidden comment: GRT188R61C475KE13D)
C57  ValueDisplayed: 100pF  [0402L]  (hidden comment: CGA2B2C0G1H101J050BA)
C58  ValueDisplayed: 4700pF  [0402L]  (hidden comment: CGA2B2X7R1H472K050BA)
C80  Cap_F: 0.1µF  [FP-GCM188L81H104KA57D_0603-MFG]  (hidden comment: GCM188L81H104KA57D)
L3  ValueDisplayed: 4.7uH  [XAL1010]  (hidden comment: XAL1010-472MEB)
NT1  Net-Tie  [Net-Tie_50milWide_30milLong]  (net tie, no BOM)
Q3  CSD18513Q5A  [DQJ0008A]
Q4  CSD18513Q5A  [DQJ0008A]
R65  ValueDisplayed: 1.00  [0201]  (hidden comment: RC0201FR-071RL)
R67  ValueDisplayed: 1.00  [0201]  (hidden comment: RC0201FR-071RL)
R68  ValueDisplayed: 147k  [0201L]  (hidden comment: RC0201FR-07147KL)
R69  ValueDisplayed: 10m  [FP-CRF1206-FZ-R010ELF_1206-MFG]  (hidden comment: CRF1206-FZ-R010ELF)
R70  ValueDisplayed: 115k  [0201L]  (hidden comment: RC0201FR-07115KL)
R71  ValueDisplayed: 102k  [0201L]  (hidden comment: RC0201FR-07102KL)
R72  ValueDisplayed: 10.0  [0201L]  (hidden comment: RC0201FS-7D10RL)
R73  ValueDisplayed: 49.9k  [0201L]  (hidden comment: RC0201FR-7D49K9L)
R74  ValueDisplayed: 56.2k  [0201L]  (hidden comment: RC0201FR-0756K2L)
R75  ValueDisplayed: 6.19k  [0201L]  (hidden comment: RC0201FR-7D6K19L)
R76  ValueDisplayed: 150k  [0201L]  (hidden comment: RC0201FR-07150KL)
R77  ValueDisplayed: 10.0  [0201L]  (hidden comment: RC0201FS-7D10RL)
R117  ValueDisplayed: 42.2k  [0201L]  (hidden comment: RC0201FR-0742K2L)
TP7  5003  [Keystone5003]  (value not drawn)
TP8  5003  [Keystone5003]  (value not drawn)
U18  TPS55288RPMR  [RPM0026A]

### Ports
GND, I2C3_SCL, I2C3_SDA, PPHV, VCC_IN

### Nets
GND: C40.2 C41.2 C42.2 C43.2(-) C45.2 C47.2 C48.2 C49.2 C50.2 C51.2 C52.2(-) C80.1 NT1.1 Q4.1(S) Q4.2(S) Q4.3(S) TP8.1 U18.9(PGND) U18.24(PGND) ; port GND
AGND: C53.2 C55.1 C56.2 C57.2 C58.2 NT1.2 R70.1 R73.1 R75.1 R76.1 R117.1 U18.10(AGND)
I2C3_SCL: U18.5(SCL) ; port I2C3_SCL
I2C3_SDA: U18.6(SDA) ; port I2C3_SDA
PPHV: C52.1(+) R69.2 R77.2 TP7.1 ; port PPHV
VCC_IN: C40.1 C41.1 C42.1 C43.1(+) C45.1 Q3.5(D) Q3.6(D) Q3.7(D) Q3.8(D) Q3.9(D) R68.2 U18.3(VIN) ; port VCC_IN
VCC_TPS55288: C56.1 R71.2 U18.19(VCC)
NetC44_1: C44.1 U18.22(BOOT1)
NetC44_2: C44.2 L3.1 Q3.1(S) Q3.2(S) Q3.3(S) Q4.5(D) Q4.6(D) Q4.7(D) Q4.8(D) Q4.9(D) U18.23(SW1)
NetC46_1: C46.1 U18.20(BOOT2)
NetC46_2: C46.2 L3.2 U18.21(SW2) U18.25(SW2)
NetC47_1: C47.1 C48.1 C49.1 C50.1 C51.1 C80.2 R69.1 R72.2 U18.11(VOUT) U18.26(VOUT)
NetC53_1: C53.1 R68.1 R70.2 U18.4(EN)
NetC54_1: C54.1 R72.1 U18.12(ISP)
NetC54_2: C54.2 R77.1 U18.13(ISN)
NetC55_2: C55.2 U18.7(DITH/SYNC)
NetC57_1: C57.1 R74.2 U18.18(COMP)
NetC58_1: C58.1 R74.1
NetQ3_4: Q3.4(G) R67.2
NetQ4_4: Q4.4(G) R65.2
NetR65_1: R65.1 U18.1(DR1L)
NetR67_1: R67.1 U18.2(DR1H)
NetR71_1: R71.1 U18.14(FB)
NetR73_2: R73.2 U18.8(FSW)
NetR75_2: R75.2 U18.15(MODE)
NetR76_2: R76.2 U18.16(CDC)
NetR117_2: R117.2 U18.17(ILIM)

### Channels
V1: designators end in _V1; ports GND=GND I2C3_SCL=I2C3_SCL I2C3_SDA=I2C3_SDA PPHV=PA_PPHV VCC_IN=VCC_IN
V2: designators end in _V2; ports GND=GND I2C3_SCL=I2C3_SCL I2C3_SDA=I2C3_SDA PPHV=PB_PPHV VCC_IN=VCC_IN

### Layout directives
net class vbus: NetC47_V1_1, PA_PPHV

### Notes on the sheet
- (near C43) VCC_IN is 12V
- Mode pin selects I2C addess. Use 6.19k for TPS #1 and 24.9k for TPS#2
- 60W: ILIM resistor 42.2k
  100W: ILIM resistor 34.4k

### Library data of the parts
C40 C41 C48-C51 = CMP-0085951-1: CAP, CERM, 10 µF, 75 V,+/- 20%, X7R, AEC-Q200 Grade 1, 1210; Manufacturer: TDK; Value2: 75V; SizeX_mm: 3.2; Cap_Case: 1210; AEC Qualified: Y; Polarized: N; AEC Category: Q200; U/M: EA; SizeZ_mm: 2.8; SizeY_mm: 2.5; TaMin_C: -55°C; AEC Grade: 1; SizeAreaWB_mm2: 14.7; SizeArea_mm2: 8; TaMax_C: 125°C; Value: 10uF
C42 C45 C47 = CMP-0081784-1: as C122 on sheet ISFA375_DS_USB-C_CONN
C43 = CMP-0012579-3: CAP, Polymer Hybrid, 68 uF, 50 V, +/- 20%, 30 ohm, 8x10 SMD; Manufacturer: Panasonic; TaMin_C: -55°C; ESR_ohm: 30; Polarized: Y; SizeAreaWB_mm2: 113.3; Value1: 30 ohm; Value: 68uF; TaMax_C: 105°C; SizeZ_mm: 10.2; SizeX_mm: 9; SizeY_mm: 8.3; Value2: 50V; SizeArea_mm2: 74.7; CompType: Capacitor; Cap_F: 68µF; IRMS_A: 1.8A; AEC Category: Q200
C44 C46 C54 C80 = CMP-0086535-1: 0.1µF ±10% 50V Ceramic Capacitor X8L 0603 (1608 Metric); Manufacturer: Murata Electronics North America; Symbol Name: SYM-GCM188L81H104KA57D; Tolerance_%: 0.1; AEC Qualified: Yes; TempCo: -40+15%; SizeZ_mm: 0.9mm; AEC Grade: Grade 0
C52 = CMP-0012571-3: CAP, Polymer Hybrid, 220 uF, 25 V, +/- 20%, 27 ohm, 8x10 SMD; Manufacturer: Panasonic; TaMin_C: -55°C; ESR_ohm: 27; Polarized: Y; SizeAreaWB_mm2: 113.3; Value1: 27 ohm; Value: 220uF; TaMax_C: 105°C; SizeZ_mm: 10.2; SizeX_mm: 9; SizeY_mm: 8.3; Value2: 25V; SizeArea_mm2: 74.7; CompType: Capacitor; Cap_F: 220µF; IRMS_A: 2.3A; AEC Category: Q200
C53 = CMP-0006325-2: as C123 on sheet ISFA375_DS_USB-C_CONN
C55 = CMP-0006324-2: CAP, CERM, 0.01 uF, 50 V, +/- 10%, X7R, AEC-Q200 Grade 1, 0402; Manufacturer: TDK; TaMin_C: -55°C; ESR_ohm: 3.33065d; Polarized: N; SizeAreaWB_mm2: 3; Value1: 0.333065 ohm; U/M: EA; Value: 0.01uF; TaMax_C: 125°C; SizeZ_mm: 0.6; SizeX_mm: 1; SizeY_mm: 0.5; Cap_Case: 0402; Value2: 50V; AEC Qualified: Y; Cap_F: 10nF; IRMS_A: 3.23373dA; AEC Category: Q200
C56 = CMP-0081052-1: CAP, CERM, 4.7 µF, 16 V,+/- 10%, X5R, AEC-Q200 Grade 3, 0603; Manufacturer: MuRata; SizeAreaWB_mm2: 4.68; SizeArea_mm2: 1.28; AEC Qualified: Y; AEC Category: Q200; Value: 4.7uF; TaMax_C: 85°C; SizeZ_mm: 1; AEC Grade: 3; Polarized: N; TaMin_C: -55°C; VDC_V: 16V; SizeY_mm: 0.8; U/M: EA; SizeX_mm: 1.6; Cap_Case: 0603
C57 = CMP-0006308-2: CAP, CERM, 100 pF, 50 V, +/- 5%, C0G/NP0, AEC-Q200 Grade 1, 0402; Manufacturer: TDK; TaMin_C: -55°C; Polarized: N; SizeAreaWB_mm2: 3; Value1: Unknown; U/M: EA; Value: 100pF; TaMax_C: 125°C; SizeZ_mm: 0.6; SizeX_mm: 1; SizeY_mm: 0.5; Cap_Case: 0402; Value2: 50V; AEC Qualified: Y; AEC Category: Q200
C58 = CMP-0006321-2: CAP, CERM, 4700 pF, 50 V, +/- 10%, X7R, AEC-Q200 Grade 1, 0402; Manufacturer: TDK; TaMin_C: -55°C; ESR_ohm: 4.13508d; Polarized: N; SizeAreaWB_mm2: 3; Value1: 0.413508 ohm; U/M: EA; Value: 4700pF; TaMax_C: 125°C; SizeZ_mm: 0.6; SizeX_mm: 1; SizeY_mm: 0.5; Cap_Case: 0402; Value2: 50V; AEC Qualified: Y; Cap_F: 4.7nF; IRMS_A: 3.30878dA; AEC Category: Q200
L3 = CMP-0060950-1: Inductor, Shielded, Composite, 4.7 uH, 24 A, 0.01 ohm, SMD; Manufacturer: Coilcraft; Isat: 25.4A @ 30% inductance drop; Green_Lifecycle: Not Set; SizeAreaWB_mm2: 159.6; DCR_ohm: 0.01; Green_REACh: Incomplete; Irms: 24A @ 40C rise; Value: 4.7uH; Imax_A: 24A; SizeZ_mm: 10; SizeX_mm: 11.3; SizeArea_mm2: 113; Ind_H: 4.7µH; AEC Category: Q200
NT1 = CMP-0078142-4: Single point connection between nets.
Q3 Q4 = CMP-0000714-1: as Q7 on sheet ISFA375_SYSTEM_POWER
R65 R67 = CMP-0027472-1: RES, 1.00, 1%, 0.05 W, 0201; Manufacturer: Yageo America; Power_W: 50mW; TempCo: 350 ppm/C; Value_Code: 1R00; U/M: EA; Value: 1.00; EIA_Code: E96; Res_ohm: 1; SizeX_mm: 0.6; SizeY_mm: 0.3; SizeZ_mm: 0.26; Value2: 0.05W; SizeArea_mm2: 0.18; AEC Qualified: N; VDC_V: 25V; AEC Category: Q200
R68 = CMP-0027358-2: RES, 147 k, 1%, 0.05 W, 0201; Manufacturer: Yageo America; Power_W: 50mW; TempCo: 200 ppm/C; U/M: EA; Value: 147k; EIA_Code: E96; SizeX_mm: 0.6; SizeY_mm: 0.3; SizeZ_mm: 0.26; Value2: 0.05W; SizeArea_mm2: 0.18; AEC Qualified: N; VDC_V: 25V; AEC Category: Q200
R69 = CMP-0086941-2: 10 mOhms ±1% 1W Chip Resistor 1206 (3216 Metric) Automotive AEC-Q200, Current Sense, Moisture Resistant Metal Element; Manufacturer: Bourns; AEC Qualified: Yes; TempCo: 50ppm/°C; AEC Grade: Grade 0; SizeZ_mm: 0.8mm
R70 = CMP-0027314-2: RES, 115 k, 1%, 0.05 W, 0201; Manufacturer: Yageo America; Power_W: 50mW; TempCo: 200 ppm/C; U/M: EA; Value: 115k; EIA_Code: E96; SizeX_mm: 0.6; SizeY_mm: 0.3; SizeZ_mm: 0.26; Value2: 0.05W; SizeArea_mm2: 0.18; AEC Qualified: N; VDC_V: 25V; AEC Category: Q200
R71 = CMP-0027295-2: RES, 102 k, 1%, 0.05 W, 0201; Manufacturer: Yageo America; Power_W: 50mW; TempCo: 200 ppm/C; U/M: EA; Value: 102k; EIA_Code: E96; SizeX_mm: 0.6; SizeY_mm: 0.3; SizeZ_mm: 0.26; Value2: 0.05W; SizeArea_mm2: 0.18; AEC Qualified: N; VDC_V: 25V; AEC Category: Q200
R72 R77 = CMP-0028072-1: RES, 10.0, 1%, 0.05 W, 0201; Manufacturer: Yageo America; Power_W: 50mW; TempCo: 350 ppm/C; Value_Code: 10R0; U/M: EA; Value: 10.0; EIA_Code: E96; Res_ohm: 10; SizeX_mm: 0.6; SizeY_mm: 0.3; SizeZ_mm: 0.26; Value2: 0.05W; SizeArea_mm2: 0.18; AEC Qualified: N; VDC_V: 25V; AEC Category: Q200
R73 = CMP-0028027-1: RES, 49.9 k, 1%, 0.05 W, 0201; Manufacturer: Yageo America; Power_W: 50mW; TempCo: 200 ppm/C; Value_Code: 49k9; U/M: EA; Value: 49.9k; EIA_Code: E96; SizeX_mm: 0.6; SizeY_mm: 0.3; SizeZ_mm: 0.26; Value2: 0.05W; SizeArea_mm2: 0.18; AEC Qualified: N; VDC_V: 25V; AEC Category: Q200
R74 = CMP-0027776-1: RES, 56.2 k, 1%, 0.05 W, 0201; Manufacturer: Yageo America; Power_W: 50mW; TempCo: 200 ppm/C; Value_Code: 56k2; U/M: EA; Value: 56.2k; EIA_Code: E96; SizeX_mm: 0.6; SizeY_mm: 0.3; SizeZ_mm: 0.26; Value2: 0.05W; SizeArea_mm2: 0.18; AEC Qualified: N; VDC_V: 25V; AEC Category: Q200
R75 = CMP-0028054-1: RES, 6.19 k, 1%, 0.05 W, 0201; Manufacturer: Yageo America; Power_W: 50mW; TempCo: 200 ppm/C; Value_Code: 6k19; U/M: EA; Value: 6.19k; EIA_Code: E96; SizeX_mm: 0.6; SizeY_mm: 0.3; SizeZ_mm: 0.26; Value2: 0.05W; SizeArea_mm2: 0.18; AEC Qualified: N; VDC_V: 25V; AEC Category: Q200
R76 = CMP-0027366-2: RES, 150 k, 1%, 0.05 W, 0201; Manufacturer: Yageo America; Power_W: 50mW; TempCo: 200 ppm/C; U/M: EA; Value: 150k; EIA_Code: E96; SizeX_mm: 0.6; SizeY_mm: 0.3; SizeZ_mm: 0.26; Value2: 0.05W; SizeArea_mm2: 0.18; AEC Qualified: N; VDC_V: 25V; AEC Category: Q200
R117 = CMP-0027696-1: RES, 42.2 k, 1%, 0.05 W, 0201; Manufacturer: Yageo America; Power_W: 50mW; TempCo: 200 ppm/C; Value_Code: 42k2; U/M: EA; Value: 42.2k; EIA_Code: E96; SizeX_mm: 0.6; SizeY_mm: 0.3; SizeZ_mm: 0.26; Value2: 0.05W; SizeArea_mm2: 0.18; AEC Qualified: N; VDC_V: 25V; AEC Category: Q200
TP7 TP8 = CMP-0055140-1: Test Point, Miniature, Orange, TH; Manufacturer: Keystone; CNHeader: FALSE; ContactFinish: Silver; CT: TRUE; Green_Lifecycle: Active; Green_REACh: Passed
U18 = CMP-0861085-2: 36-V, 16-A Buck-Boost Converter, RPM0026A (VQFN-HR-26); Manufacturer: Texas Instruments; SizeY_mm: 3.5; SizeArea_mm2: 14; AEC Category: Q200; SizeX_mm: 4; CompType: IC; AEC Qualified: N; SizeZ_mm: 1

## Sheet ISFA375_REDRIVER_TUSB1104.SchDoc
size 431 x 279 mm; Date: Not shown in title block; ApprovedBy: Not shown in title block; CheckedBy: Not shown in title block; Author: Not shown in title block; CompanyName: Not shown in title block; DrawnBy: Thomas Mauer; Engineer: Not shown in title block; Organization: Not shown in title block; Address1: Not shown in title block; Address2: Not shown in title block; Address3: Not shown in title block; Address4: Not shown in title block; DocumentNumber: 3; Revision: Use project parameter SCH_Rev; SheetNumber: 3; SheetTotal: 11; PageSetup: Record=PageOptions¦CenterHorizontal=True¦CenterVertical=True¦PrintScale=1.00¦XCorrection=1.00¦YCorrection=1.00¦PrintKind=0¦BorderSize=5000000¦LeftOffset=0¦BottomOffset=0¦Orientation=2¦PaperLength=1000¦PaperWidth=1000¦Scale=100¦PaperSource=15¦PrintQuality=600¦MediaType=1¦DitherType=10¦PaperKind=Letter¦PrintScaleMode=1
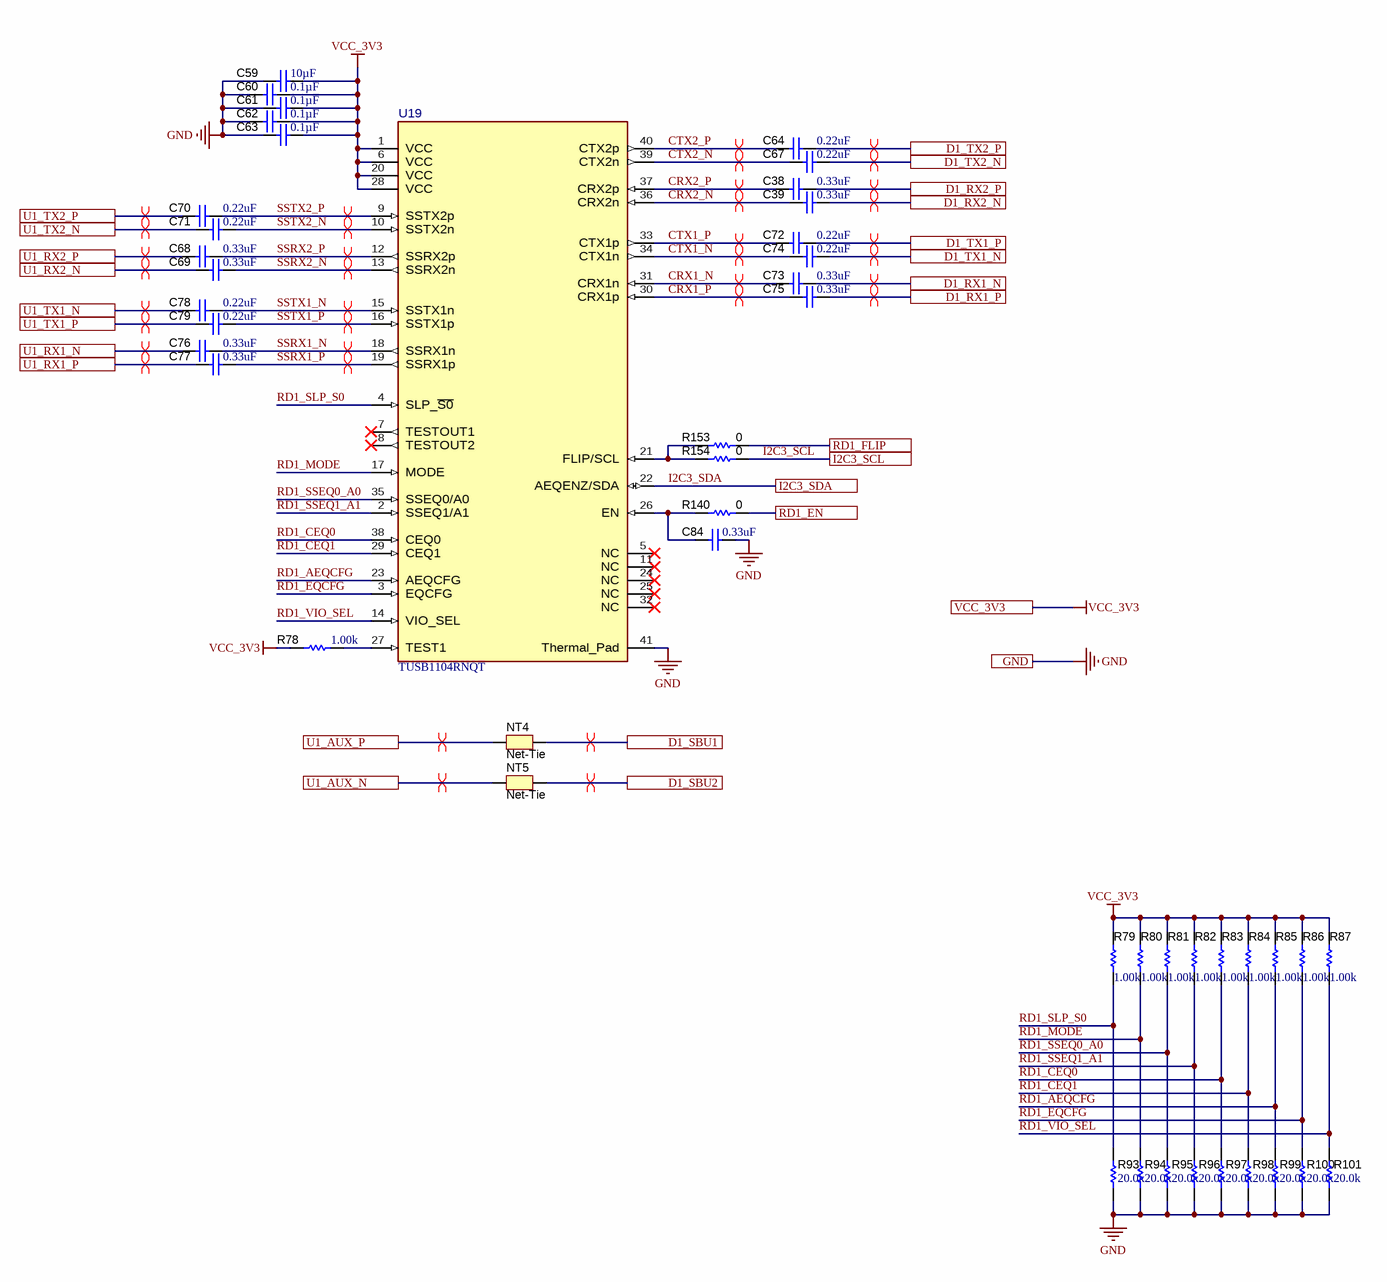
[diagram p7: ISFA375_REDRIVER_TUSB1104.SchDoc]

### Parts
C38  ValueDisplayed: 0.33uF  [0201_033L]  (hidden comment: C0603X5R1A334K030BC)
C39  ValueDisplayed: 0.33uF  [0201_033L]  (hidden comment: C0603X5R1A334K030BC)
C59  Cap_F: 10µF  [0805L]  (hidden comment: CL21B106KOQNNNE)
C60  ValueDisplayed: 0.1µF  [0201_033L]  (hidden comment: GRM033R61A104KE84D)
C61  ValueDisplayed: 0.1µF  [0201_033L]  (hidden comment: GRM033R61A104KE84D)
C62  ValueDisplayed: 0.1µF  [0201_033L]  (hidden comment: GRM033R61A104KE84D)
C63  ValueDisplayed: 0.1µF  [0201_033L]  (hidden comment: GRM033R61A104KE84D)
C64  ValueDisplayed: 0.22uF  [0201_033L]  (hidden comment: LMK063BJ224MP-F)
C67  ValueDisplayed: 0.22uF  [0201_033L]  (hidden comment: LMK063BJ224MP-F)
C68  ValueDisplayed: 0.33uF  [0201_033L]  (hidden comment: C0603X5R1A334K030BC)
C69  ValueDisplayed: 0.33uF  [0201_033L]  (hidden comment: C0603X5R1A334K030BC)
C70  ValueDisplayed: 0.22uF  [0201_033L]  (hidden comment: LMK063BJ224MP-F)
C71  ValueDisplayed: 0.22uF  [0201_033L]  (hidden comment: LMK063BJ224MP-F)
C72  ValueDisplayed: 0.22uF  [0201_033L]  (hidden comment: LMK063BJ224MP-F)
C73  ValueDisplayed: 0.33uF  [0201_033L]  (hidden comment: C0603X5R1A334K030BC)
C74  ValueDisplayed: 0.22uF  [0201_033L]  (hidden comment: LMK063BJ224MP-F)
C75  ValueDisplayed: 0.33uF  [0201_033L]  (hidden comment: C0603X5R1A334K030BC)
C76  ValueDisplayed: 0.33uF  [0201_033L]  (hidden comment: C0603X5R1A334K030BC)
C77  ValueDisplayed: 0.33uF  [0201_033L]  (hidden comment: C0603X5R1A334K030BC)
C78  ValueDisplayed: 0.22uF  [0201_033L]  (hidden comment: LMK063BJ224MP-F)
C79  ValueDisplayed: 0.22uF  [0201_033L]  (hidden comment: LMK063BJ224MP-F)
C84  ValueDisplayed: 0.33uF  [0201_033L]  (hidden comment: C0603X5R1A334K030BC)
NT4  Net-Tie  [Net-Tie6milsWide_20milsLong]  (net tie, no BOM)
NT5  Net-Tie  [Net-Tie6milsWide_20milsLong]  (net tie, no BOM)
R78  ValueDisplayed: 1.00k  [0201L]  (hidden comment: CRCW02011K00FKED)
R79  ValueDisplayed: 1.00k  [0201L]  (hidden comment: CRCW02011K00FKED)
R80  ValueDisplayed: 1.00k  [0201L]  (hidden comment: CRCW02011K00FKED)
R81  ValueDisplayed: 1.00k  [0201L]  (hidden comment: CRCW02011K00FKED)
R82  ValueDisplayed: 1.00k  [0201L]  (hidden comment: CRCW02011K00FKED)
R83  ValueDisplayed: 1.00k  [0201L]  (hidden comment: CRCW02011K00FKED)
R84  ValueDisplayed: 1.00k  [0201L]  (hidden comment: CRCW02011K00FKED)
R85  ValueDisplayed: 1.00k  [0201L]  (hidden comment: CRCW02011K00FKED)
R86  ValueDisplayed: 1.00k  [0201L]  (hidden comment: CRCW02011K00FKED)
R87  ValueDisplayed: 1.00k  [0201L]  (hidden comment: CRCW02011K00FKED)
R93  ValueDisplayed: 20.0k  [0201L]  (hidden comment: CRCW020120K0FKED)
R94  ValueDisplayed: 20.0k  [0201L]  (hidden comment: CRCW020120K0FKED)
R95  ValueDisplayed: 20.0k  [0201L]  (hidden comment: CRCW020120K0FKED)
R96  ValueDisplayed: 20.0k  [0201L]  (hidden comment: CRCW020120K0FKED)
R97  ValueDisplayed: 20.0k  [0201L]  (hidden comment: CRCW020120K0FKED)
R98  ValueDisplayed: 20.0k  [0201L]  (hidden comment: CRCW020120K0FKED)
R99  ValueDisplayed: 20.0k  [0201L]  (hidden comment: CRCW020120K0FKED)
R100  ValueDisplayed: 20.0k  [0201L]  (hidden comment: CRCW020120K0FKED)
R101  ValueDisplayed: 20.0k  [0201L]  (hidden comment: CRCW020120K0FKED)
R140  ValueDisplayed: 0  [0201L]  (hidden comment: CRCW02010000Z0ED)
R153  ValueDisplayed: 0  [0201L]  (hidden comment: CRCW02010000Z0ED)
R154  ValueDisplayed: 0  [0201L]  (hidden comment: CRCW02010000Z0ED)
U19  TUSB1104RNQT  [RNQ0040A-MFG]

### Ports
D1_RX1_N, D1_RX1_P, D1_RX2_N, D1_RX2_P, D1_SBU1, D1_SBU2, D1_TX1_N, D1_TX1_P, D1_TX2_N, D1_TX2_P, GND, I2C3_SCL, I2C3_SDA, RD1_EN, RD1_FLIP, U1_AUX_N, U1_AUX_P, U1_RX1_N, U1_RX1_P, U1_RX2_N, U1_RX2_P, U1_TX1_N, U1_TX1_P, U1_TX2_N, U1_TX2_P, VCC_3V3

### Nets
GND: C59.2 C60.2 C61.2 C62.2 C63.2 C84.1 R93.1 R94.1 R95.1 R96.1 R97.1 R98.1 R99.1 R100.1 R101.1 U19.41(Thermal_Pad) ; port GND
VCC_3V3: C59.1 C60.1 C61.1 C62.1 C63.1 R78.1 R79.2 R80.2 R81.2 R82.2 R83.2 R84.2 R85.2 R86.2 R87.2 U19.1(VCC) U19.6(VCC) U19.20(VCC) U19.28(VCC) ; port VCC_3V3  [project net VCC_3.3V]
AUX_N: NT5.1 ; port U1_AUX_N
AUX_N: NT5.2 ; port D1_SBU2  [a separate net that carries the same name]
AUX_P: NT4.1 ; port U1_AUX_P
AUX_P: NT4.2 ; port D1_SBU1  [a separate net that carries the same name]
CRX1_N: C73.2 U19.31(CRX1n)
CRX1_P: C75.2 U19.30(CRX1p)
CRX2_N: C39.2 U19.36(CRX2n)
CRX2_P: C38.2 U19.37(CRX2p)
CTX1_N: C74.2 U19.34(CTX1n)
CTX1_P: C72.2 U19.33(CTX1p)
CTX2_N: C67.2 U19.39(CTX2n)
CTX2_P: C64.2 U19.40(CTX2p)
D1_RX1_N: C73.1 ; port D1_RX1_N
D1_RX1_P: C75.1 ; port D1_RX1_P
D1_RX2_N: C39.1 ; port D1_RX2_N
D1_RX2_P: C38.1 ; port D1_RX2_P
D1_TX1_N: C74.1 ; port D1_TX1_N
D1_TX1_P: C72.1 ; port D1_TX1_P
D1_TX2_N: C67.1 ; port D1_TX2_N
D1_TX2_P: C64.1 ; port D1_TX2_P
I2C3_SCL: R154.2 ; port I2C3_SCL
I2C3_SDA: U19.22(AEQENZ/SDA) ; port I2C3_SDA
RD1_AEQCFG: R85.1 R99.2 U19.23(AEQCFG)
RD1_CEQ0: R83.1 R97.2 U19.38(CEQ0)
RD1_CEQ1: R84.1 R98.2 U19.29(CEQ1)
RD1_EN: R140.2 ; port RD1_EN
RD1_EQCFG: R86.1 R100.2 U19.3(EQCFG)
RD1_FLIP: R153.2 ; port RD1_FLIP
RD1_MODE: R80.1 R94.2 U19.17(MODE)
RD1_SLP_S0: R79.1 R93.2 U19.4(SLP_~{S0})
RD1_SSEQ0_A0: R81.1 R95.2 U19.35(SSEQ0/A0)
RD1_SSEQ1_A1: R82.1 R96.2 U19.2(SSEQ1/A1)
RD1_VIO_SEL: R87.1 R101.2 U19.14(VIO_SEL)
RX1_N: C76.2 ; port U1_RX1_N
RX1_P: C77.2 ; port U1_RX1_P
RX2_N: C69.2 ; port U1_RX2_N
RX2_P: C68.2 ; port U1_RX2_P
SSRX1_N: C76.1 U19.18(SSRX1n)
SSRX1_P: C77.1 U19.19(SSRX1p)
SSRX2_N: C69.1 U19.13(SSRX2n)
SSRX2_P: C68.1 U19.12(SSRX2p)
SSTX1_N: C78.1 U19.15(SSTX1n)
SSTX1_P: C79.1 U19.16(SSTX1p)
SSTX2_N: C71.1 U19.10(SSTX2n)
SSTX2_P: C70.1 U19.9(SSTX2p)
TX1_N: C78.2 ; port U1_TX1_N
TX1_P: C79.2 ; port U1_TX1_P
TX2_N: C71.2 ; port U1_TX2_N
TX2_P: C70.2 ; port U1_TX2_P
NetC84_2: C84.2 R140.1 U19.26(EN)
NetR78_2: R78.2 U19.27(TEST1)
NetR153_1: R153.1 R154.1 U19.21(FLIP/SCL)

Not connected (* = marked no-connect by the designer): U19 5(NC)* 7(TESTOUT1)* 8(TESTOUT2)* 11(NC)* 24(NC)* 25(NC)* 32(NC)*

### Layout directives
differential pair; net class Diff_pairs: CRX1_N, CRX1_P, CRX2_N, CRX2_P, CTX1_N, CTX1_P, CTX2_N, CTX2_P, D1_RX1_N, D1_RX1_P, D1_RX2_N, D1_RX2_P, D1_TX1_N, D1_TX1_P, D1_TX2_N, D1_TX2_P, RX1_N, RX1_P, RX2_N, RX2_P, SSRX1_N, SSRX1_P, SSRX2_N, SSRX2_P, SSTX1_N, SSTX1_P, SSTX2_N, SSTX2_P, TX1_N, TX1_P, TX2_N, TX2_P
differential pair: AUX_N, AUX_P

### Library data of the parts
C38 C39 C68 C69 C73 C75-C77 C84 = CMP-0009635-3: CAP, CERM, 0.33 uF, 10 V, +/- 10%, X5R, 0201; Manufacturer: TDK; TaMin_C: -55°C; Polarized: N; SizeAreaWB_mm2: 2.08; Value1: Unknown; U/M: EA; Value: 0.33uF; TaMax_C: 85°C; SizeZ_mm: 0.33; SizeX_mm: 0.6; SizeY_mm: 0.3; Cap_Case: 0201; Value2: 10V; SizeArea_mm2: 0.18; Cap_F: 330nF; AEC Category: Q200
C59 = CMP-0007995-2: CAP, CERM, 10 uF, 16 V, +/- 10%, X7R, 0805; Manufacturer: Samsung Electro-Mechanics; TaMin_C: -55°C; Polarized: N; SizeAreaWB_mm2: 6.75; Value1: Unknown; U/M: EA; Value: 10uF; TaMax_C: 125°C; SizeZ_mm: 1.45; SizeX_mm: 2; SizeY_mm: 1.25; Cap_Case: 0805; Value2: 16V; SizeArea_mm2: 2.5; AEC Category: Q200
C60-C63 = CMP-0086059-1: as C87 on sheet ISFA375_SYSTEM_POWER
C64 C67 C70-C72 C74 C78 C79 = CMP-0009781-1: CAP, CERM, 0.22 uF, 10 V, +/- 20%, X5R, 0201; Manufacturer: Taiyo Yuden; TaMin_C: -55°C; Polarized: N; SizeAreaWB_mm2: 2.08; Value1: Unknown; U/M: EA; Value: 0.22uF; TaMax_C: 85°C; SizeZ_mm: 0.33; SizeX_mm: 0.6; SizeY_mm: 0.3; Cap_Case: 0201; Value2: 10V; SizeArea_mm2: 0.18; Cap_F: 220nF; AEC Category: Q200
NT4 NT5 = CMP-0078142-4: Single point connection between nets.
R78-R87 = CMP-0027267-3: RES, 1.00 k, 1%, 0.05 W, 0201; Manufacturer: Vishay-Dale; Power_W: 50mW; TempCo: 100 ppm/C; Value_Code: 1k00; Value: 1.00k; EIA_Code: E96; Res_ohm: 1k; SizeX_mm: 0.6; SizeY_mm: 0.3; SizeZ_mm: 0.26; Value2: 0.05W; SizeArea_mm2: 0.18; AEC Qualified: N; VDC_V: 30V; AEC Category: Q200
R93-R101 = CMP-0027269-3: RES, 20.0 k, 1%, 0.05 W, 0201; Manufacturer: Vishay-Dale; Power_W: 50mW; TempCo: 100 ppm/C; Value_Code: 20k0; Value: 20.0k; EIA_Code: E96; Res_ohm: 20k; SizeX_mm: 0.6; SizeY_mm: 0.3; SizeZ_mm: 0.26; Value2: 0.05W; SizeArea_mm2: 0.18; AEC Qualified: N; VDC_V: 30V; AEC Category: Q200
R140 R153 R154 = CMP-0027008-4: as R159 on sheet ISFA375_DS_USB-C_CONN
U19 = CMP-0092691-1: USB Type-C 10Gbps USB3.2 x2 Adaptive Linear Redriver; Manufacturer: Texas Instruments; Number Of Ports: 2; Data Rate: 20Gbits/s; Interface: I2C,USB; TaMin_C: 0°C; AEC Qualified: No; Min Supply Voltage: 1.7V; TaMax_C: +70°C; TJmax_C: +105°C; SizeZ_mm: 0.8mm; Max Supply Voltage: 3.6V; Usb Standard: OTHER; Standoff Height: 0mm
